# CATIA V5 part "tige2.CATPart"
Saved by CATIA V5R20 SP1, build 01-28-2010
Part number: tige2
Bounding box of the stored display mesh (mm): x -12.5 to 0.765, y 80.145 to 773.235, z -92.069 to 49.474
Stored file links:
  C:\Users\Fox\Desktop\IAO Projet\A RENDRE\Sauvegarde IFMA\tige2.CATPart
  C:\Users\Fox\Desktop\IAO Projet\A RENDRE\Sauvegarde IFMA\mpeyrard.CATProduct
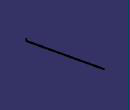
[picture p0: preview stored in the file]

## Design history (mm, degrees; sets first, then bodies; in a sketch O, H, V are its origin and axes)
Set1
  Plane1: linked copy from another document
  Line1 to Line3: linked copy from another document
Body1 (main body)
  Sketch1 on Plane1, origin (0, 54.6358, -87.6583), H (1, 0, 0), V (0, 0.9812, 0.1931)
    axis line L1 (-7.2344, 30.4671) -> (-27.2495, 30.4671)
    reference projected point E1 (0, 30.4671) from Line2
    reference projected line E2 (0, 5.4671) -> (0, 30.4671) from Line3
    circle A1 centre (-10, 30.4671) radius 2.5
    point P3 (-10, 30.4671)
    reference projected point E3 (0, 30.4671) from Line2
    distance E1 L1 = 0
    radius A1 = 2.5
    distance E3 P3 = 10
    perpendicularity: E2 L1
    coincidence: P3 L1
  Pad1: profile Sketch1, direction (0, -0.1931, 0.9812), length 10, mirrored extent
  Sketch2 on start face of Pad1, origin (0, 60.1191, -96.771), H (-1, 0, 0), V (0, 0.9812, 0.1931)
    axis line L1 (4.4314, 26.8468) -> (27.134, 26.8468)
    reference projected line E1 (0, 5.4671) -> (0, 30.4671) from Line3
    reference projected point E2 (0, 26.8468) from Line2
    line L2 (12.5005, 26.8468) -> (7.5005, 26.8468)
    line L3 (7.5005, 26.8468) -> (-0.7645, 726.798)
    line L4 (-0.7645, 726.798) -> (4.2355, 726.798)
    line L5 (4.2355, 726.798) -> (12.5005, 26.8468)
    reference projected line E3 through (0.3168, 0.0205) direction (-0.0118, 0.9999) from Line1
    reference projected point E4 (0, 26.8468) from Line2
    distance L1 E2 = 0
    length L2 = 5
    distance L2 L1 = 0
    distance L3 E4 = 7.5
    length L5 = 700
    perpendicularity: L1 E1
    horizontal: L2 H, L4 H
    parallelism: E3 L3, L5 L3
  Pad2: profile Sketch2, direction (0, -0.1931, 0.9812), length 6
